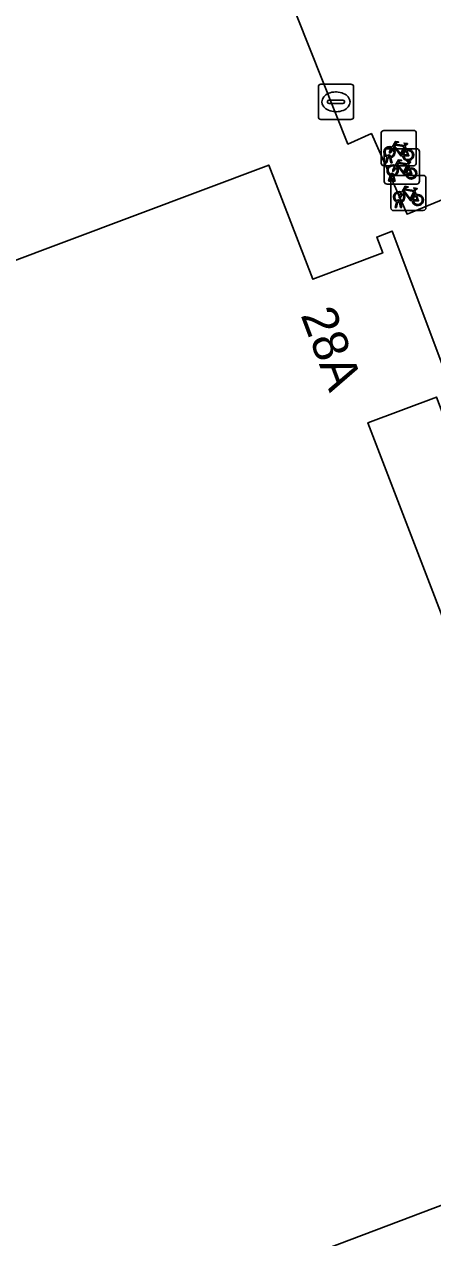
# Model space of a CAD drawing. Extents: x 161347 to 161881, y 382161 to 382804.
# Drawn here: x 161778.23 to 161789.84, y 382511.92 to 382546.37 of the extents above; entities that cross this region are included whole.
import ezdxf

# ---------------------------------------------------------------- set-up
doc = ezdxf.new("R2010")
doc.units = 0
for name, color, linetype in [('IMGEO_Erf', 7, 'Continuous'), ('IMGEO_Fietsenrek', 7, 'Continuous'), ('IMGEO_Pand', 7, 'Continuous'), ('IMGEO_Pand_nummerreeks', 7, 'Continuous'), ('IMGEO_Rioolput', 7, 'Continuous'), ('IMGEO_Voetpad_open', 7, 'Continuous')]:
    doc.layers.add(name, color=color, linetype=linetype)

msp = doc.modelspace()

# ---------------------------------------------------------------- linework, layer by layer
at = {"layer": 'IMGEO_Erf'}
for points in [[(161794.971, 382530.118), (161792.241, 382536.131), (161792.378, 382536.972), (161792.323, 382537.821), (161791.654, 382539.638), (161791.061, 382540.405), (161790.328, 382541.011), (161790.189, 382541.423), (161789.107, 382540.979), (161788.094, 382543.265), (161787.424, 382542.968), (161782.001, 382556.605), (161781.188, 382558.978), (161780.231, 382559.421), (161779.298, 382559.715), (161776.187, 382560.249), (161770.93, 382560.454), (161716.681, 382562.374), (161709.058, 382555.75), (161702.444, 382550.002), (161681.121, 382531.471), (161671.366, 382522.817), (161670.351, 382521.638), (161669.529, 382520.317)], [(161764.271, 382534.527), (161785.178, 382542.374), (161786.424, 382539.134), (161788.413, 382539.88), (161788.244, 382540.331), (161788.686, 382540.497), (161790.549, 382535.529), (161790.101, 382535.361), (161789.941, 382535.787), (161787.992, 382535.056), (161795.715, 382514.974), (161766.605, 382503.972)]]:
    msp.add_lwpolyline(points, dxfattribs=at)
at = {"layer": 'IMGEO_Fietsenrek'}
for p, q in [((161788.443, 382543.355), (161789.284, 382543.355)), ((161789.284, 382543.355), (161788.443, 382543.355)), ((161788.368, 382542.43), (161788.368, 382543.271)), ((161788.368, 382543.271), (161788.368, 382542.43)), ((161789.368, 382543.28), (161789.368, 382542.439)), ((161789.368, 382542.439), (161789.368, 382543.28)), ((161788.455, 382541.909), (161788.455, 382542.75)), ((161788.455, 382542.75), (161788.455, 382541.909)), ((161788.53, 382542.834), (161789.371, 382542.834)), ((161789.371, 382542.834), (161788.53, 382542.834)), ((161789.055, 382542.904), (161789.091, 382542.809)), ((161789.455, 382542.759), (161789.455, 382541.918)), ((161789.455, 382541.918), (161789.455, 382542.759)), ((161789.293, 382542.355), (161788.452, 382542.355)), ((161788.452, 382542.355), (161789.293, 382542.355)), ((161788.495, 382542.439), (161788.534, 382542.599)), ((161788.529, 382542.439), (161788.495, 382542.439)), ((161788.564, 382542.587), (161788.529, 382542.439)), ((161788.606, 382542.611), (161788.605, 382542.615)), ((161788.647, 382542.439), (161788.613, 382542.581)), ((161788.637, 382542.622), (161788.638, 382542.615)), ((161788.645, 382542.585), (161788.68, 382542.439)), ((161788.68, 382542.439), (161788.647, 382542.439)), ((161789.142, 382542.383), (161789.178, 382542.288)), ((161788.582, 382541.918), (161788.621, 382542.078)), ((161788.651, 382542.066), (161788.616, 382541.918)), ((161788.642, 382541.156), (161788.642, 382541.997)), ((161788.642, 382541.997), (161788.642, 382541.156)), ((161788.693, 382542.09), (161788.692, 382542.094)), ((161788.734, 382541.918), (161788.7, 382542.06)), ((161788.717, 382542.081), (161789.558, 382542.081)), ((161789.558, 382542.081), (161788.717, 382542.081)), ((161788.724, 382542.101), (161788.725, 382542.094)), ((161788.732, 382542.064), (161788.767, 382541.918)), ((161789.642, 382542.006), (161789.642, 382541.165)), ((161789.642, 382541.165), (161789.642, 382542.006)), ((161789.38, 382541.834), (161788.539, 382541.834)), ((161788.539, 382541.834), (161789.38, 382541.834)), ((161788.616, 382541.918), (161788.582, 382541.918)), ((161788.767, 382541.918), (161788.734, 382541.918)), ((161789.329, 382541.63), (161789.365, 382541.535)), ((161788.769, 382541.165), (161788.808, 382541.325)), ((161788.838, 382541.313), (161788.803, 382541.165)), ((161788.88, 382541.337), (161788.879, 382541.341)), ((161788.921, 382541.165), (161788.887, 382541.307)), ((161788.911, 382541.348), (161788.912, 382541.341)), ((161788.919, 382541.311), (161788.954, 382541.165)), ((161789.567, 382541.081), (161788.726, 382541.081)), ((161788.726, 382541.081), (161789.567, 382541.081)), ((161788.803, 382541.165), (161788.769, 382541.165)), ((161788.954, 382541.165), (161788.921, 382541.165))]:
    msp.add_line(p, q, dxfattribs=at)
for points in [[(161788.681, 382542.881), (161788.776, 382543.045), (161788.862, 382543.031), (161788.864, 382543.022), (161788.808, 382543.011), (161788.781, 382542.966), (161789.037, 382542.925)], [(161789.037, 382542.925), (161789.062, 382542.974), (161789.056, 382542.978), (161789.033, 382542.982), (161789.021, 382542.989), (161789.02, 382542.992), (161789.022, 382542.997), (161789.117, 382542.982), (161789.119, 382542.972), (161789.109, 382542.959), (161789.097, 382542.953), (161789.083, 382542.959), (161789.055, 382542.904)], [(161788.702, 382542.829), (161788.65, 382542.739), (161788.61, 382542.714), (161788.611, 382542.761), (161788.666, 382542.855)], [(161788.977, 382542.637), (161788.927, 382542.637), (161788.736, 382542.888), (161788.717, 382542.856)], [(161789.024, 382542.9), (161788.767, 382542.941), (161788.75, 382542.912), (161788.917, 382542.692), (161789.024, 382542.9)], [(161789.072, 382542.802), (161789.042, 382542.879), (161788.933, 382542.661), (161788.976, 382542.661)], [(161789.006, 382542.661), (161789.126, 382542.66), (161789.082, 382542.774)], [(161789.102, 382542.781), (161789.157, 382542.636), (161789.007, 382542.636)], [(161788.789, 382542.308), (161788.737, 382542.218), (161788.697, 382542.193), (161788.698, 382542.24), (161788.753, 382542.334)], [(161788.768, 382542.36), (161788.863, 382542.524), (161788.949, 382542.51), (161788.951, 382542.501), (161788.895, 382542.49), (161788.868, 382542.445), (161789.124, 382542.404)], [(161789.064, 382542.116), (161789.014, 382542.116), (161788.823, 382542.367), (161788.804, 382542.335)], [(161789.111, 382542.379), (161788.854, 382542.42), (161788.837, 382542.391), (161789.004, 382542.171), (161789.111, 382542.379)], [(161789.159, 382542.281), (161789.129, 382542.358), (161789.02, 382542.14), (161789.063, 382542.14)], [(161789.124, 382542.404), (161789.149, 382542.453), (161789.143, 382542.457), (161789.12, 382542.461), (161789.108, 382542.468), (161789.107, 382542.471), (161789.109, 382542.476), (161789.204, 382542.461), (161789.206, 382542.451), (161789.196, 382542.438), (161789.184, 382542.432), (161789.17, 382542.438), (161789.142, 382542.383)], [(161789.093, 382542.14), (161789.213, 382542.139), (161789.169, 382542.253)], [(161789.189, 382542.26), (161789.244, 382542.115), (161789.094, 382542.115)], [(161788.955, 382541.607), (161789.05, 382541.771), (161789.136, 382541.757), (161789.138, 382541.748), (161789.082, 382541.737), (161789.055, 382541.692), (161789.311, 382541.651)], [(161789.251, 382541.363), (161789.201, 382541.363), (161789.01, 382541.614), (161788.991, 382541.582)], [(161789.298, 382541.626), (161789.041, 382541.667), (161789.024, 382541.638), (161789.191, 382541.418), (161789.298, 382541.626)], [(161789.311, 382541.651), (161789.336, 382541.7), (161789.33, 382541.704), (161789.307, 382541.708), (161789.295, 382541.715), (161789.294, 382541.718), (161789.296, 382541.723), (161789.391, 382541.708), (161789.393, 382541.698), (161789.383, 382541.685), (161789.371, 382541.679), (161789.357, 382541.685), (161789.329, 382541.63)], [(161788.976, 382541.555), (161788.924, 382541.465), (161788.884, 382541.44), (161788.885, 382541.487), (161788.94, 382541.581)], [(161789.346, 382541.528), (161789.316, 382541.605), (161789.207, 382541.387), (161789.25, 382541.387)], [(161789.28, 382541.387), (161789.4, 382541.386), (161789.356, 382541.5)], [(161789.376, 382541.507), (161789.431, 382541.362), (161789.281, 382541.362)]]:
    msp.add_lwpolyline(points, dxfattribs=at)
for centre, radius, start, end in [((161788.446, 382543.277), 0.0779, 92.4484, 184.2845), ((161788.446, 382543.277), 0.0779, 92.4484, 184.2845), ((161789.29, 382543.277), 0.0779, 2.4484, 94.2845), ((161789.29, 382543.277), 0.0779, 2.4484, 94.2845), ((161788.608, 382542.74), 0.159, 62.6766, 242.1369), ((161788.533, 382542.756), 0.0779, 92.4484, 184.2845), ((161788.533, 382542.756), 0.0779, 92.4484, 184.2845), ((161788.608, 382542.74), 0.129, 63.3192, 238.903), ((161788.588, 382542.611), 0.0499, 12.8025, 158.6934), ((161788.608, 382542.74), 0.129, 283.6043, 43.4302), ((161788.608, 382542.74), 0.159, 283.5766, 46.6042), ((161789.135, 382542.656), 0.159, 113.3408, 178.3217), ((161789.135, 382542.656), 0.159, 187.0065, 105.7708), ((161789.135, 382542.656), 0.129, 113.923, 177.9556), ((161789.135, 382542.656), 0.129, 188.6715, 104.5883), ((161789.377, 382542.756), 0.0779, 2.4484, 94.2845), ((161789.377, 382542.756), 0.0779, 2.4484, 94.2845), ((161788.446, 382542.433), 0.0779, 182.4484, 274.2845), ((161788.446, 382542.433), 0.0779, 182.4484, 274.2845), ((161788.695, 382542.219), 0.159, 62.6766, 242.1369), ((161788.608, 382542.74), 0.159, 253.9967, 271.7867), ((161788.695, 382542.219), 0.129, 63.3192, 238.903), ((161788.588, 382542.611), 0.0174, 12.8025, 163.4502), ((161788.608, 382542.74), 0.129, 253.415, 269.0204), ((161788.695, 382542.219), 0.129, 283.6043, 43.4302), ((161788.695, 382542.219), 0.159, 283.5766, 46.6042), ((161789.29, 382542.433), 0.0779, 272.4484, 4.2845), ((161789.29, 382542.433), 0.0779, 272.4484, 4.2845), ((161788.675, 382542.09), 0.0499, 12.8025, 158.6934), ((161788.72, 382542.003), 0.0779, 92.4484, 184.2845), ((161788.72, 382542.003), 0.0779, 92.4484, 184.2845), ((161788.695, 382542.219), 0.159, 253.9967, 271.7867), ((161788.675, 382542.09), 0.0174, 12.8025, 163.4502), ((161788.695, 382542.219), 0.129, 253.415, 269.0204), ((161789.222, 382542.135), 0.159, 113.3408, 178.3217), ((161789.222, 382542.135), 0.159, 187.0065, 105.7708), ((161789.222, 382542.135), 0.129, 113.923, 177.9556), ((161789.222, 382542.135), 0.129, 188.6715, 104.5883), ((161789.564, 382542.003), 0.0779, 2.4484, 94.2845), ((161789.564, 382542.003), 0.0779, 2.4484, 94.2845), ((161788.533, 382541.912), 0.0779, 182.4484, 274.2845), ((161788.533, 382541.912), 0.0779, 182.4484, 274.2845), ((161788.882, 382541.466), 0.159, 62.6766, 242.1369), ((161789.377, 382541.912), 0.0779, 272.4484, 4.2845), ((161789.377, 382541.912), 0.0779, 272.4484, 4.2845), ((161788.882, 382541.466), 0.129, 63.3192, 238.903), ((161788.862, 382541.337), 0.0499, 12.8025, 158.6934), ((161788.882, 382541.466), 0.159, 253.9967, 271.7867), ((161788.862, 382541.337), 0.0174, 12.8025, 163.4502), ((161788.882, 382541.466), 0.129, 253.415, 269.0204), ((161788.882, 382541.466), 0.129, 283.6043, 43.4302), ((161788.882, 382541.466), 0.159, 283.5766, 46.6042), ((161789.409, 382541.382), 0.159, 113.3408, 178.3217), ((161789.409, 382541.382), 0.159, 187.0065, 105.7708), ((161789.409, 382541.382), 0.129, 113.923, 177.9556), ((161789.409, 382541.382), 0.129, 188.6715, 104.5883), ((161788.72, 382541.159), 0.0779, 182.4484, 274.2845), ((161788.72, 382541.159), 0.0779, 182.4484, 274.2845), ((161789.564, 382541.159), 0.0779, 272.4484, 4.2845), ((161789.564, 382541.159), 0.0779, 272.4484, 4.2845)]:
    msp.add_arc(centre, radius, start, end, dxfattribs=at)
at = {"layer": 'IMGEO_Pand'}
msp.add_lwpolyline([(161766.605, 382503.972), (161795.715, 382514.974), (161787.992, 382535.056), (161789.941, 382535.787), (161790.101, 382535.361), (161790.549, 382535.529), (161788.686, 382540.497), (161788.244, 382540.331), (161788.413, 382539.88), (161786.424, 382539.134), (161785.178, 382542.374), (161764.271, 382534.527)], dxfattribs=at)
at = {"layer": 'IMGEO_Rioolput'}
for p, q in [((161786.585, 382543.742), (161786.585, 382544.594)), ((161786.66, 382544.668), (161787.512, 382544.668)), ((161787.073, 382544.448), (161787.098, 382544.448)), ((161787.586, 382544.594), (161787.586, 382543.742)), ((161786.844, 382544.162), (161786.844, 382544.174)), ((161787.282, 382544.125), (161786.884, 382544.125)), ((161786.887, 382544.211), (161787.285, 382544.211)), ((161787.328, 382544.174), (161787.328, 382544.162)), ((161787.096, 382543.888), (161787.071, 382543.888)), ((161787.512, 382543.668), (161786.66, 382543.668))]:
    msp.add_line(p, q, dxfattribs=at)
for points in [[(161786.585, 382543.742), (161786.585, 382544.594)], [(161786.66, 382544.668), (161787.512, 382544.668)], [(161787.586, 382544.594), (161787.586, 382543.742)], [(161787.512, 382543.668), (161786.66, 382543.668)]]:
    msp.add_lwpolyline(points, dxfattribs=at)
for centre, radius, start, end in [((161786.662, 382544.592), 0.0765, 91.552, 178.448), ((161786.662, 382544.592), 0.0765, 91.552, 178.448), ((161787.51, 382544.592), 0.0765, 1.552, 88.448), ((161787.51, 382544.592), 0.0765, 1.552, 88.448), ((161786.884, 382544.171), 0.0403, 85.8775, 175.7526), ((161786.881, 382544.161), 0.0366, 178.938, 274.7102), ((161787.285, 382544.168), 0.043, 264.8664, 352.4533), ((161787.289, 382544.173), 0.0386, 1.7309, 96.639), ((161786.662, 382543.744), 0.0765, 181.552, 268.448), ((161786.662, 382543.744), 0.0765, 181.552, 268.448), ((161787.51, 382543.744), 0.0765, 271.552, 358.448), ((161787.51, 382543.744), 0.0765, 271.552, 358.448)]:
    msp.add_arc(centre, radius, start, end, dxfattribs=at)
for centre, major_axis, ratio, start_param, end_param in [((161787.072, 382544.168), (-0.387, 0.002), 0.722429, 4.712389, 7.853982), ((161787.097, 382544.168), (-0.39, 0.002), 0.717154, 1.570796, 4.712389)]:
    msp.add_ellipse(centre, major_axis=major_axis, ratio=ratio, start_param=start_param, end_param=end_param, dxfattribs=at)
at = {"layer": 'IMGEO_Voetpad_open'}
msp.add_lwpolyline([(161789.046, 382556.024), (161782.001, 382556.605), (161787.424, 382542.968), (161788.094, 382543.265), (161789.107, 382540.979), (161790.189, 382541.423), (161790.328, 382541.011), (161791.061, 382540.405), (161791.654, 382539.638), (161792.323, 382537.821), (161792.378, 382536.972), (161792.241, 382536.131), (161794.971, 382530.118), (161801.747, 382512.319)], dxfattribs=at)

# ---------------------------------------------------------------- texts
at = {"layer": 'IMGEO_Pand_nummerreeks'}
msp.add_text('28A', height=1, rotation=290.556, dxfattribs=at).set_placement((161786.075, 382538.118))

doc.saveas('drawing.dxf')
